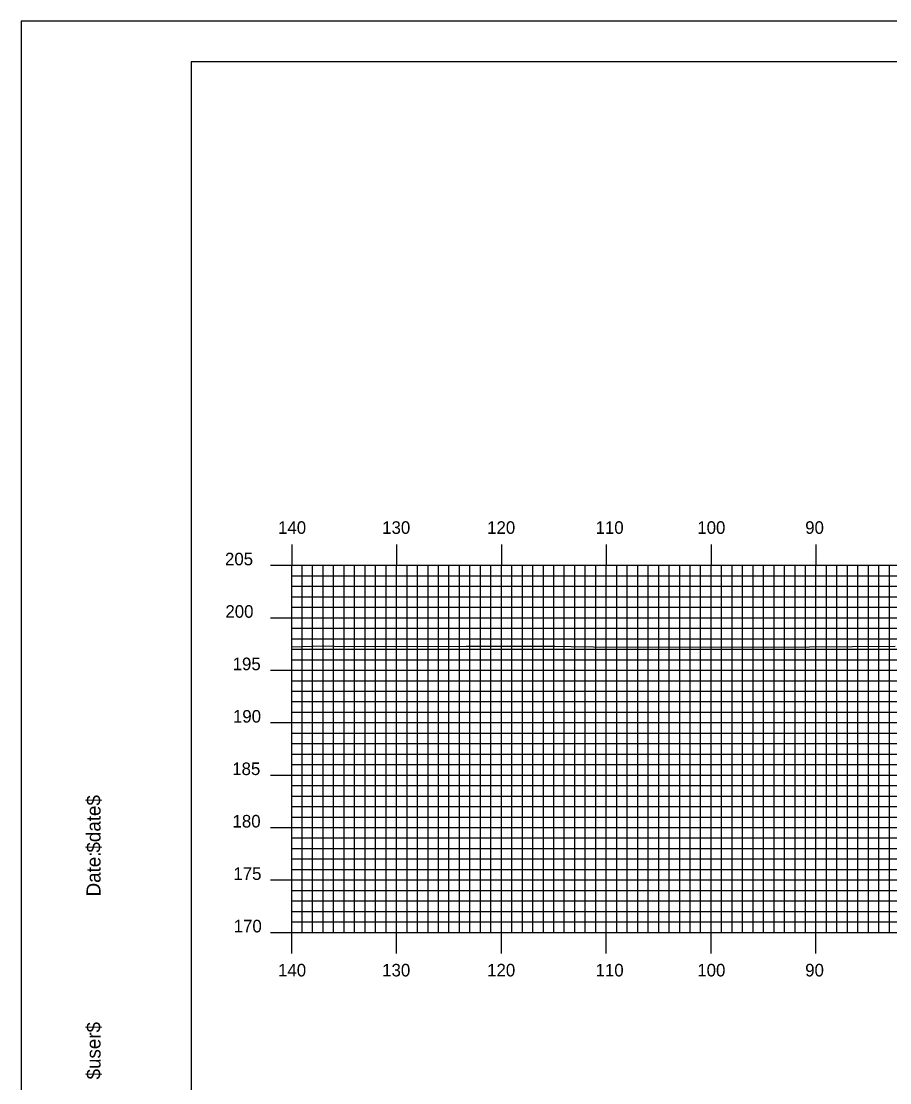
# Model space of a CAD drawing. Extents: x 1796420 to 1796763, y 442591 to 442811.
# Drawn here: x 1796420.1 to 1796502.9, y 442709.3 to 442810.5 of the extents above; entities that cross this region are included whole.
import ezdxf

# ---------------------------------------------------------------- set-up
doc = ezdxf.new("R2010")
doc.units = 0
for name, color, linetype in [('BORDER', 7, 'Continuous'), ('H_V ANNOTATION', 7, 'Continuous'), ('MAJOR', 7, 'Continuous'), ('MINOR', 7, 'Continuous'), ('PLOT BOUNDARY', 7, 'Continuous'), ('S_Roadway_Centerline', 7, 'Continuous')]:
    doc.layers.add(name, color=color, linetype=linetype)

msp = doc.modelspace()

# ---------------------------------------------------------------- linework, layer by layer
at = {"layer": 'BORDER'}
msp.add_lwpolyline([(1796436.31, 442596.67), (1796756.31, 442596.67), (1796756.31, 442806.67), (1796436.31, 442806.67)], close=True, dxfattribs=at)
at = {"layer": 'MAJOR'}
for p, q in [((1796445.91, 442760.67), (1796445.91, 442758.67)), ((1796455.91, 442760.67), (1796455.91, 442758.67)), ((1796465.91, 442760.67), (1796465.91, 442758.67)), ((1796475.91, 442760.67), (1796475.91, 442758.67)), ((1796485.91, 442760.67), (1796485.91, 442758.67)), ((1796495.91, 442760.67), (1796495.91, 442758.67)), ((1796443.9, 442758.67), (1796445.91, 442758.67)), ((1796445.91, 442758.67), (1796725.91, 442758.67)), ((1796445.91, 442723.67), (1796445.91, 442758.67)), ((1796445.91, 442723.67), (1796445.91, 442758.67)), ((1796445.91, 442758.67), (1796725.91, 442758.67)), ((1796455.91, 442723.67), (1796455.91, 442758.67)), ((1796465.91, 442723.67), (1796465.91, 442758.67)), ((1796475.91, 442723.67), (1796475.91, 442758.67)), ((1796485.91, 442723.67), (1796485.91, 442758.67)), ((1796495.91, 442723.67), (1796495.91, 442758.67)), ((1796443.9, 442753.67), (1796445.91, 442753.67)), ((1796445.91, 442753.67), (1796725.91, 442753.67)), ((1796443.9, 442748.67), (1796445.91, 442748.67)), ((1796445.91, 442748.67), (1796725.91, 442748.67)), ((1796443.9, 442743.67), (1796445.91, 442743.67)), ((1796445.91, 442743.67), (1796725.91, 442743.67)), ((1796443.9, 442738.67), (1796445.91, 442738.67)), ((1796445.91, 442738.67), (1796725.91, 442738.67)), ((1796443.9, 442733.67), (1796445.91, 442733.67)), ((1796445.91, 442733.67), (1796725.91, 442733.67)), ((1796443.9, 442728.67), (1796445.91, 442728.67)), ((1796445.91, 442728.67), (1796725.91, 442728.67)), ((1796443.9, 442723.67), (1796445.91, 442723.67)), ((1796445.91, 442723.67), (1796725.91, 442723.67)), ((1796445.91, 442723.67), (1796725.91, 442723.67)), ((1796445.91, 442721.66), (1796445.91, 442723.67)), ((1796455.91, 442721.66), (1796455.91, 442723.67)), ((1796465.91, 442721.66), (1796465.91, 442723.67)), ((1796475.91, 442721.66), (1796475.91, 442723.67)), ((1796485.91, 442721.66), (1796485.91, 442723.67)), ((1796495.91, 442721.66), (1796495.91, 442723.67))]:
    msp.add_line(p, q, dxfattribs=at)
at = {"layer": 'MINOR'}
for p, q in [((1796446.91, 442723.67), (1796446.91, 442758.67)), ((1796447.91, 442723.67), (1796447.91, 442758.67)), ((1796448.91, 442723.67), (1796448.91, 442758.67)), ((1796449.91, 442723.67), (1796449.91, 442758.67)), ((1796450.91, 442723.67), (1796450.91, 442758.67)), ((1796451.91, 442723.67), (1796451.91, 442758.67)), ((1796452.91, 442723.67), (1796452.91, 442758.67)), ((1796453.91, 442723.67), (1796453.91, 442758.67)), ((1796454.91, 442723.67), (1796454.91, 442758.67)), ((1796456.91, 442723.67), (1796456.91, 442758.67)), ((1796457.91, 442723.67), (1796457.91, 442758.67)), ((1796458.91, 442723.67), (1796458.91, 442758.67)), ((1796459.91, 442723.67), (1796459.91, 442758.67)), ((1796460.91, 442723.67), (1796460.91, 442758.67)), ((1796461.91, 442723.67), (1796461.91, 442758.67)), ((1796462.91, 442723.67), (1796462.91, 442758.67)), ((1796463.91, 442723.67), (1796463.91, 442758.67)), ((1796464.91, 442723.67), (1796464.91, 442758.67)), ((1796466.91, 442723.67), (1796466.91, 442758.67)), ((1796467.91, 442723.67), (1796467.91, 442758.67)), ((1796468.91, 442723.67), (1796468.91, 442758.67)), ((1796469.91, 442723.67), (1796469.91, 442758.67)), ((1796470.91, 442723.67), (1796470.91, 442758.67)), ((1796471.91, 442723.67), (1796471.91, 442758.67)), ((1796472.91, 442723.67), (1796472.91, 442758.67)), ((1796473.91, 442723.67), (1796473.91, 442758.67)), ((1796474.91, 442723.67), (1796474.91, 442758.67)), ((1796476.91, 442723.67), (1796476.91, 442758.67)), ((1796477.91, 442723.67), (1796477.91, 442758.67)), ((1796478.91, 442723.67), (1796478.91, 442758.67)), ((1796479.91, 442723.67), (1796479.91, 442758.67)), ((1796480.91, 442723.67), (1796480.91, 442758.67)), ((1796481.91, 442723.67), (1796481.91, 442758.67)), ((1796482.91, 442723.67), (1796482.91, 442758.67)), ((1796483.91, 442723.67), (1796483.91, 442758.67)), ((1796484.91, 442723.67), (1796484.91, 442758.67)), ((1796486.91, 442723.67), (1796486.91, 442758.67)), ((1796487.91, 442723.67), (1796487.91, 442758.67)), ((1796488.91, 442723.67), (1796488.91, 442758.67)), ((1796489.91, 442723.67), (1796489.91, 442758.67)), ((1796490.91, 442723.67), (1796490.91, 442758.67)), ((1796491.91, 442723.67), (1796491.91, 442758.67)), ((1796492.91, 442723.67), (1796492.91, 442758.67)), ((1796493.91, 442723.67), (1796493.91, 442758.67)), ((1796494.91, 442723.67), (1796494.91, 442758.67)), ((1796496.91, 442723.67), (1796496.91, 442758.67)), ((1796497.91, 442723.67), (1796497.91, 442758.67)), ((1796498.91, 442723.67), (1796498.91, 442758.67)), ((1796499.91, 442723.67), (1796499.91, 442758.67)), ((1796500.91, 442723.67), (1796500.91, 442758.67)), ((1796501.91, 442723.67), (1796501.91, 442758.67)), ((1796502.91, 442723.67), (1796502.91, 442758.67)), ((1796445.91, 442757.67), (1796725.91, 442757.67)), ((1796445.91, 442757.67), (1796447.91, 442757.67)), ((1796445.91, 442756.67), (1796725.91, 442756.67)), ((1796445.91, 442756.67), (1796447.91, 442756.67)), ((1796445.91, 442755.67), (1796725.91, 442755.67)), ((1796445.91, 442755.67), (1796447.91, 442755.67)), ((1796445.91, 442754.67), (1796725.91, 442754.67)), ((1796445.91, 442754.67), (1796447.91, 442754.67)), ((1796445.91, 442752.67), (1796725.91, 442752.67)), ((1796445.91, 442752.67), (1796447.91, 442752.67)), ((1796445.91, 442751.67), (1796725.91, 442751.67)), ((1796445.91, 442751.67), (1796447.91, 442751.67)), ((1796445.91, 442750.67), (1796725.91, 442750.67)), ((1796445.91, 442750.67), (1796447.91, 442750.67)), ((1796445.91, 442749.67), (1796725.91, 442749.67)), ((1796445.91, 442749.67), (1796447.91, 442749.67)), ((1796445.91, 442747.67), (1796725.91, 442747.67)), ((1796445.91, 442747.67), (1796447.91, 442747.67)), ((1796445.91, 442746.67), (1796725.91, 442746.67)), ((1796445.91, 442746.67), (1796447.91, 442746.67)), ((1796445.91, 442745.67), (1796725.91, 442745.67)), ((1796445.91, 442745.67), (1796447.91, 442745.67)), ((1796445.91, 442744.67), (1796725.91, 442744.67)), ((1796445.91, 442744.67), (1796447.91, 442744.67)), ((1796445.91, 442742.67), (1796725.91, 442742.67)), ((1796445.91, 442742.67), (1796447.91, 442742.67)), ((1796445.91, 442741.67), (1796725.91, 442741.67)), ((1796445.91, 442741.67), (1796447.91, 442741.67)), ((1796445.91, 442740.67), (1796725.91, 442740.67)), ((1796445.91, 442740.67), (1796447.91, 442740.67)), ((1796445.91, 442739.67), (1796725.91, 442739.67)), ((1796445.91, 442739.67), (1796447.91, 442739.67)), ((1796445.91, 442737.67), (1796725.91, 442737.67)), ((1796445.91, 442737.67), (1796447.91, 442737.67)), ((1796445.91, 442736.67), (1796725.91, 442736.67)), ((1796445.91, 442736.67), (1796447.91, 442736.67)), ((1796445.91, 442735.67), (1796725.91, 442735.67)), ((1796445.91, 442735.67), (1796447.91, 442735.67)), ((1796445.91, 442734.67), (1796725.91, 442734.67)), ((1796445.91, 442734.67), (1796447.91, 442734.67)), ((1796445.91, 442732.67), (1796725.91, 442732.67)), ((1796445.91, 442732.67), (1796447.91, 442732.67)), ((1796445.91, 442731.67), (1796725.91, 442731.67)), ((1796445.91, 442731.67), (1796447.91, 442731.67)), ((1796445.91, 442730.67), (1796725.91, 442730.67)), ((1796445.91, 442730.67), (1796447.91, 442730.67)), ((1796445.91, 442729.67), (1796725.91, 442729.67)), ((1796445.91, 442729.67), (1796447.91, 442729.67)), ((1796445.91, 442727.67), (1796725.91, 442727.67)), ((1796445.91, 442727.67), (1796447.91, 442727.67)), ((1796445.91, 442726.67), (1796725.91, 442726.67)), ((1796445.91, 442726.67), (1796447.91, 442726.67)), ((1796445.91, 442725.67), (1796725.91, 442725.67)), ((1796445.91, 442725.67), (1796447.91, 442725.67)), ((1796445.91, 442724.67), (1796725.91, 442724.67)), ((1796445.91, 442724.67), (1796447.91, 442724.67))]:
    msp.add_line(p, q, dxfattribs=at)
at = {"layer": 'PLOT BOUNDARY'}
msp.add_lwpolyline([(1796420.12, 442590.55), (1796760.12, 442590.55), (1796760.12, 442810.55), (1796420.12, 442810.55)], close=True, dxfattribs=at)
at = {"layer": 'S_Roadway_Centerline'}
msp.add_lwpolyline([(1796445.91, 442750.9), (1796445.93, 442750.9), (1796448.98, 442750.98), (1796450.98, 442750.94), (1796462.54, 442750.95), (1796471.02, 442750.97), (1796472.55, 442750.93), (1796474.68, 442750.9), (1796491.21, 442750.88), (1796503.46, 442750.97)], dxfattribs=at)

# ---------------------------------------------------------------- texts
at = {"layer": 'BORDER'}
for s, p in [('$date$', (1796427.68, 442731.28)), ('Date:', (1796427.68, 442727.1)), ('$user$', (1796427.68, 442709.65))]:
    msp.add_text(s, height=1.339, rotation=90, dxfattribs=at).set_placement(p)
at = {"layer": 'H_V ANNOTATION'}
for s, p in [('140', (1796444.61, 442761.67)), ('130', (1796454.54, 442761.67)), ('120', (1796464.55, 442761.67)), ('110', (1796474.89, 442761.67)), ('100', (1796484.59, 442761.67)), ('90', (1796494.88, 442761.67)), ('205', (1796439.55, 442758.67)), ('200', (1796439.59, 442753.67)), ('195', (1796440.28, 442748.67)), ('190', (1796440.31, 442743.67)), ('185', (1796440.24, 442738.67)), ('180', (1796440.27, 442733.67)), ('175', (1796440.35, 442728.67)), ('170', (1796440.38, 442723.67)), ('140', (1796444.61, 442719.47)), ('130', (1796454.54, 442719.47)), ('120', (1796464.55, 442719.47)), ('110', (1796474.89, 442719.47)), ('100', (1796484.59, 442719.47)), ('90', (1796494.88, 442719.47))]:
    msp.add_text(s, height=1.2, dxfattribs=at).set_placement(p)
at = {"layer": 'MAJOR'}
msp.add_text('-', height=0.012, dxfattribs=at).set_placement((1796445.9, 442723.67))

doc.saveas('drawing.dxf')
